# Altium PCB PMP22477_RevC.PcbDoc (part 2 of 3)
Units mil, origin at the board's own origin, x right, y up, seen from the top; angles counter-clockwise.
Board outline 5000 x 3000 mil, 4 copper layers (Top Layer, Signal Layer 1, Signal Layer 2, Bottom Layer), stack 61.2 mil thick; 191 components, 134 nets, 569 pads, 237 vias.
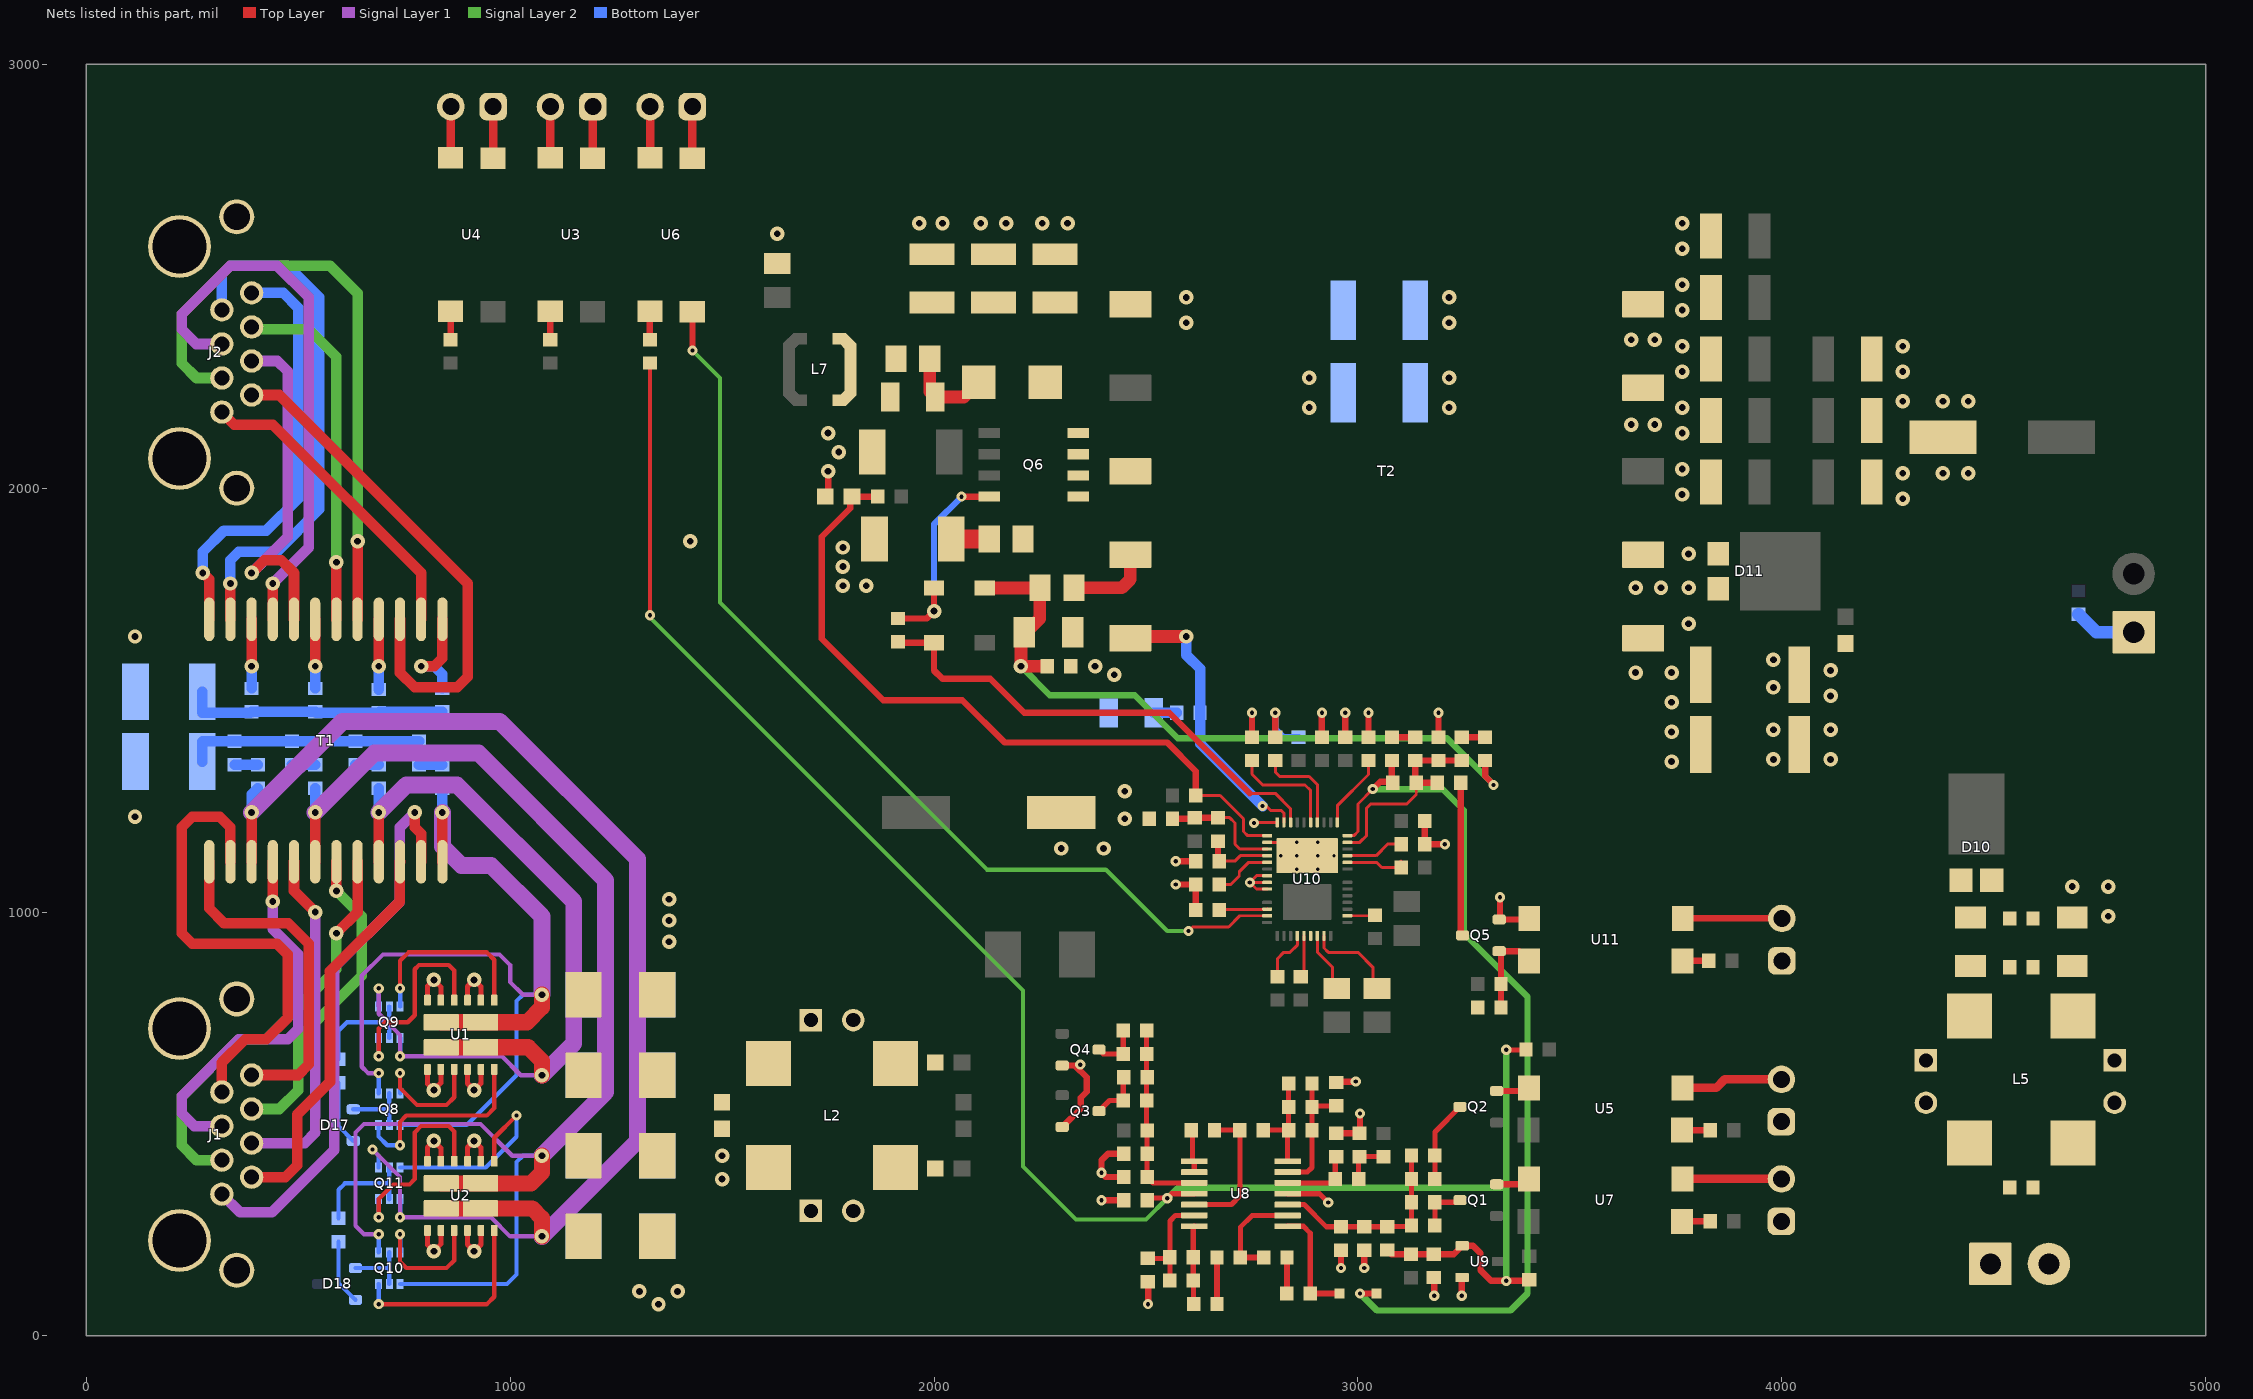
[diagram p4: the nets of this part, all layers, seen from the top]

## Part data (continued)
Q1 Q2 Q3 Q4 Q5: library part CMP-0000769-1, "MOSFET, N-CH, 60 V, 0.17 A, SOT-23", Alternate Manufacturer=None, Manufacturer="Diodes Inc.", Supplier Part Number 1=2N7002-FDICT-ND, Value1=7, Value2="223 nC"
Q6: library part CMP-0001058-1, "MOSFET, N-CH, 150 V, 4.6 A, PQFN08A", Alternate Manufacturer=None, Manufacturer="Fairchild Semiconductor", Supplier Part Number 1=FDMS86252CT-ND, Value1=0, Value2="11 nC"
Q8 Q9 Q10 Q11: library part CMP-0000518-2, "Transistor, NPN/PNP Pair, 65 V, 0.1 A, SOT-363", Manufacturer="Infineon Technologies", Supplier Part Number 1="BC 846PN H6327CT-ND", Value1="0.1 A", Value2=450
R1 R2 R3 R4 R5 R6 R7 R8: library part CMP-0022590-4, "RES, 75.0, 1%, 0.1 W, AEC-Q200 Grade 0, 0603", Manufacturer=Vishay-Dale, PartNumber=CRCW060375R0FKEA, Power_W=100mW, Supplier Part Number 1=541-75.0HCT-ND, TempCo="100 ppm/C", Tolerance_%=1%, Value2=0.1W, Value_Code=75R0, ValueDisplayed=75.0
R9 R10 R11 R12 R13 R15 R20 R35 R44 R56: library part CMP-0021998-4, "RES, 10.0 k, 1%, 0.1 W, AEC-Q200 Grade 0, 0603", Manufacturer=Vishay-Dale, Power_W=100mW, Supplier Part Number 1=541-10.0KHCT-ND, TempCo="100 ppm/C", Tolerance_%=1%, Value2=0.1W, Value_Code=10k0, ValueDisplayed=10.0k
R14 R58: library part CMP-0022458-4, "RES, 4.99 k, 1%, 0.1 W, AEC-Q200 Grade 0, 0603", Manufacturer=Vishay-Dale, Power_W=100mW, Supplier Part Number 1=541-4.99KHCT-ND, TempCo="100 ppm/C", Tolerance_%=1%, Value2=0.1W, Value_Code=4k99, ValueDisplayed=4.99k
R17: library part CMP-0018666-3, "RES, 39 k, 5%, 0.25 W, AEC-Q200 Grade 0, 1206", Manufacturer=Vishay-Dale, PartNumber=CRCW120639K0JNEA, Power_W=250mW, Supplier Part Number 1=541-39KECT-ND, TempCo="200 ppm/C", Tolerance_%=5%, Value2=0.25W, Value_Code=39k0, ValueDisplayed=39k
R18 R26 R34 R38 R39 R40 R72: library part CMP-0022109-5, "RES, 1.00 k, 1%, 0.1 W, AEC-Q200 Grade 0, 0603", Manufacturer=Vishay-Dale, Power_W=100mW, Supplier Part Number 1=541-1.00KHCT-ND, TempCo="100 ppm/C", Tolerance_%=1%, Value2=0.1W, Value_Code=1k00, ValueDisplayed=1.00k
R19: library part CMP-0021990-4, "RES, 100 k, 1%, 0.1 W, AEC-Q200 Grade 0, 0603", Manufacturer=Vishay-Dale, Power_W=100mW, Supplier Part Number 1=541-100KHCT-ND, TempCo="100 ppm/C", Tolerance_%=1%, Value2=0.1W, Value_Code=100k
R21: library part CMP-0022103-4, "RES, 196 k, 1%, 0.1 W, AEC-Q200 Grade 0, 0603", Manufacturer=Vishay-Dale, Power_W=100mW, Supplier Part Number 1=541-196KHCT-ND, TempCo="100 ppm/C", Tolerance_%=1%, Value2=0.1W, Value_Code=196k
R22: library part CMP-0022634-4, "RES, 8.06 k, 1%, 0.1 W, AEC-Q200 Grade 0, 0603", Manufacturer=Vishay-Dale, Power_W=100mW, Supplier Part Number 1=541-8.06KHCT-ND, TempCo="100 ppm/C", Tolerance_%=1%, Value2=0.1W, Value_Code=8k06, ValueDisplayed=8.06k
R23 R36: library part CMP-0022138-4, "RES, 1.00 M, 1%, 0.1 W, AEC-Q200 Grade 0, 0603", Manufacturer=Vishay-Dale, Power_W=100mW, Supplier Part Number 1=541-1.00MHCT-ND, TempCo="100 ppm/C", Tolerance_%=1%, Value2=0.1W, Value_Code=1M00, ValueDisplayed=1.00M
R24: library part CMP-0022284-4, "RES, 2.94 k, 1%, 0.1 W, AEC-Q200 Grade 0, 0603", Manufacturer=Vishay-Dale, Power_W=100mW, Supplier Part Number 1=541-2.94KHCT-ND, TempCo="100 ppm/C", Tolerance_%=1%, Value2=0.1W, Value_Code=2k94, ValueDisplayed=2.94k
R25 R30 R37: library part CMP-0022410-4, "RES, 40.2 k, 1%, 0.1 W, AEC-Q200 Grade 0, 0603", Manufacturer=Vishay-Dale, Power_W=100mW, Supplier Part Number 1=541-40.2KHCT-ND, TempCo="100 ppm/C", Tolerance_%=1%, Value2=0.1W, Value_Code=40k2, ValueDisplayed=40.2k
R27: library part CMP-0022451-4, "RES, 4.22 k, 1%, 0.1 W, AEC-Q200 Grade 0, 0603", Manufacturer=Vishay-Dale, Power_W=100mW, Supplier Part Number 1=541-4.22KHCT-ND, TempCo="100 ppm/C", Tolerance_%=1%, Value2=0.1W, Value_Code=4k22, ValueDisplayed=4.22k
R28: library part CMP-0022256-4, "RES, 280 k, 1%, 0.1 W, AEC-Q200 Grade 0, 0603", Manufacturer=Vishay-Dale, Power_W=100mW, Supplier Part Number 1=541-280KHCT-ND, TempCo="100 ppm/C", Tolerance_%=1%, Value2=0.1W, Value_Code=280k
R29: library part CMP-0022383-4, "RES, 3.92 k, 1%, 0.1 W, AEC-Q200 Grade 0, 0603", Manufacturer=Vishay-Dale, Power_W=100mW, Supplier Part Number 1=541-3.92KHCT-ND, TempCo="100 ppm/C", Tolerance_%=1%, Value2=0.1W, Value_Code=3k92, ValueDisplayed=3.92k
R31: library part CMP-0022131-4, "RES, 1.69 k, 1%, 0.1 W, AEC-Q200 Grade 0, 0603", Manufacturer=Vishay-Dale, Power_W=100mW, Supplier Part Number 1=541-1.69KHCT-ND, TempCo="100 ppm/C", Tolerance_%=1%, Value2=0.1W, Value_Code=1k69, ValueDisplayed=1.69k
R32 R33: library part CMP-0021991-4, "RES, 100, 1%, 0.1 W, AEC-Q200 Grade 0, 0603", Manufacturer=Vishay-Dale, Power_W=100mW, Supplier Part Number 1=541-100HCT-ND, TempCo="100 ppm/C", Tolerance_%=1%, Value2=0.1W, Value_Code=100R, ValueDisplayed=100
R41: library part CMP-0022008-4, "RES, 110 k, 1%, 0.1 W, AEC-Q200 Grade 0, 0603", Manufacturer=Vishay-Dale, Power_W=100mW, Supplier Part Number 1=541-110KHCT-ND, TempCo="100 ppm/C", Tolerance_%=1%, Value2=0.1W, Value_Code=110k
R42 R43: library part CMP-0015887-3, "RES, 15, 5%, 1 W, AEC-Q200 Grade 0, 2512", Manufacturer=Vishay-Dale, Power_W=1W, Supplier Part Number 1=541-15XCT-ND, TempCo="200 ppm/C", Tolerance_%=5%, Value_Code=15R0, ValueDisplayed=15
R45: library part CMP-0021831-3, "RES, 3.90, 1%, 0.125 W, AEC-Q200 Grade 0, 0805", Manufacturer=Panasonic, Power_W=125mW, Supplier Part Number 1=P3.9DCT-ND, TempCo="200 ppm/C", Tolerance_%=1%, Value2=0.125W, Value_Code=3R90, ValueDisplayed=3.90
R46: library part CMP-0018668-3, "RES, 3.0 k, 5%, 0.25 W, AEC-Q200 Grade 0, 1206", Manufacturer=Vishay-Dale, Power_W=250mW, Supplier Part Number 1=541-3.0KECT-ND, TempCo="200 ppm/C", Tolerance_%=5%, Value2=0.25W, Value_Code=3k00, ValueDisplayed=3.0k
R47: library part CMP-0022369-4, "RES, 39.2 k, 1%, 0.1 W, AEC-Q200 Grade 0, 0603", Manufacturer=Vishay-Dale, Power_W=100mW, Supplier Part Number 1=541-39.2KHCT-ND, TempCo="100 ppm/C", Tolerance_%=1%, Value2=0.1W, Value_Code=39k2, ValueDisplayed=39.2k
R48 R49 R52 R55 R59 R60 R65 R73 R101: library part CMP-0025874-4, "RES, 0, 5%, 0.1 W, AEC-Q200 Grade 0, 0603", Manufacturer=Panasonic, Power_W=100mW, Supplier Part Number 1=P0.0GCT-ND, TempCo="600 ppm/C", Tolerance_%=5%, Value2=0.1W, Value_Code=0000, ValueDisplayed=0
R50: library part CMP-0022944-5, "RES, 24.9 k, 1%, 0.1 W, 0603", Manufacturer=Yageo, Power_W=100mW, Supplier Part Number 1=311-24.9KHRCT-ND, TempCo="100 ppm/C", Tolerance_%=1%, Value2=0.1W, Value_Code=24k9, ValueDisplayed=24.9k
R51: library part CMP-0022931-4, "RES, 237 k, 1%, 0.1 W, 0603", Manufacturer=Yageo, Power_W=100mW, Supplier Part Number 1=311-237KHRCT-ND, TempCo="100 ppm/C", Tolerance_%=1%, Value2=0.1W, Value_Code=237k
R53: library part CMP-0022532-4, "RES, 60.4 k, 1%, 0.1 W, AEC-Q200 Grade 0, 0603", Manufacturer=Vishay-Dale, Power_W=100mW, Supplier Part Number 1=541-60.4KHCT-ND, TempCo="100 ppm/C", Tolerance_%=1%, Value2=0.1W, Value_Code=60k4, ValueDisplayed=60.4k
R54: library part CMP-0023050-5, "RES, 35.7 k, 1%, 0.1 W, 0603", Manufacturer=Yageo, Power_W=100mW, Supplier Part Number 1=311-35.7KHRCT-ND, TempCo="100 ppm/C", Tolerance_%=1%, Value2=0.1W, Value_Code=35k7, ValueDisplayed=35.7k
R57 R62: library part CMP-0022204-4, "RES, 20.0 k, 1%, 0.1 W, AEC-Q200 Grade 0, 0603", Manufacturer=Vishay-Dale, Power_W=100mW, Supplier Part Number 1=541-20.0KHCT-ND, TempCo="100 ppm/C", Tolerance_%=1%, Value2=0.1W, Value_Code=20k0, ValueDisplayed=20.0k
R61: library part CMP-0025821-4, "RES, 4.7, 5%, 0.1 W, AEC-Q200 Grade 0, 0603", Manufacturer=Vishay-Dale, Power_W=100mW, Supplier Part Number 1=541-4.7GCT-ND, TempCo="200 ppm/C", Tolerance_%=5%, Value2=0.1W, Value_Code=4R70, ValueDisplayed=4.7
R63: library part CMP-0016178-3, "RES, 75, 5%, 0.75 W, AEC-Q200 Grade 0, 2010", Manufacturer=Vishay-Dale, Power_W=750mW, Supplier Part Number 1=541-75.0WCT-ND, TempCo="200 ppm/C", Tolerance_%=5%, Value2=0.75W, Value_Code=75R0, ValueDisplayed=75
R64: library part CMP-0022447-4, "RES, 49.9 k, 1%, 0.1 W, AEC-Q200 Grade 0, 0603", Manufacturer=Vishay-Dale, Power_W=100mW, Supplier Part Number 1=541-49.9KHCT-ND, TempCo="100 ppm/C", Tolerance_%=1%, Value2=0.1W, Value_Code=49k9, ValueDisplayed=49.9k
R66: library part CMP-0018594-3, "RES, 15, 5%, 0.25 W, AEC-Q200 Grade 0, 1206", Manufacturer=Vishay-Dale, Power_W=250mW, Supplier Part Number 1=541-15ECT-ND, TempCo="200 ppm/C", Tolerance_%=5%, Value2=0.25W, Value_Code=15R0, ValueDisplayed=15
R67: library part CMP-0016520-2, "RES, 0.05, 1%, 1 W, 2010", Manufacturer="Stackpole Electronics Inc", Power_W=1W, Supplier Part Number 1=CSRN2010FK50L0CT-ND, TempCo="250 ppm/C", Tolerance_%=1%, Value_Code=R050, ValueDisplayed=0.05
R68: library part CMP-0021169-3, "RES, 31.6, 1%, 0.125 W, AEC-Q200 Grade 0, 0805", Manufacturer=Vishay-Dale, Power_W=125mW, Supplier Part Number 1=541-31.6CCT-ND, TempCo="100 ppm/C", Tolerance_%=1%, Value2=0.125W, Value_Code=31R6, ValueDisplayed=31.6
R69: library part CMP-0020880-3, "RES, 130, 1%, 0.125 W, AEC-Q200 Grade 0, 0805", Manufacturer=Vishay-Dale, Power_W=125mW, Supplier Part Number 1=541-130CCT-ND, TempCo="100 ppm/C", Tolerance_%=1%, Value2=0.125W, Value_Code=130R, ValueDisplayed=130
R70: library part CMP-0025851-4, "RES, 750 k, 5%, 0.1 W, AEC-Q200 Grade 0, 0603", Manufacturer=Vishay-Dale, Power_W=100mW, Supplier Part Number 1=541-750KGCT-ND, TempCo="200 ppm/C", Tolerance_%=5%, Value2=0.1W, Value_Code=750k
R71: library part CMP-0022951-5, "RES, 25.5 k, 1%, 0.1 W, 0603", Manufacturer=Yageo, Power_W=100mW, Supplier Part Number 1=311-25.5KHRCT-ND, TempCo="100 ppm/C", Tolerance_%=1%, Value2=0.1W, Value_Code=25k5, ValueDisplayed=25.5k
R74: library part CMP-0022445-4, "RES, 499 k, 1%, 0.1 W, AEC-Q200 Grade 0, 0603", Manufacturer=Vishay-Dale, Power_W=100mW, Supplier Part Number 1=541-499KHCT-ND, TempCo="100 ppm/C", Tolerance_%=1%, Value2=0.1W, Value_Code=499k
R75 R76: library part CMP-0022073-4, "RES, 162 k, 1%, 0.1 W, AEC-Q200 Grade 0, 0603", Manufacturer=Vishay-Dale, Power_W=100mW, Supplier Part Number 1=541-162KHCT-ND, TempCo="100 ppm/C", Tolerance_%=1%, Value2=0.1W, Value_Code=162k
R100: library part CMP-0022371-4, "RES, 3.01 k, 1%, 0.1 W, AEC-Q200 Grade 0, 0603", Manufacturer=Vishay-Dale, Power_W=100mW, Supplier Part Number 1=541-3.01KHCT-ND, TempCo="100 ppm/C", Tolerance_%=1%, Value2=0.1W, Value_Code=3k01, ValueDisplayed=3.01k
T1: library part CMP-0030730-1, "Transformer, PoE+, SMT", Manufacturer="Wurth Elektronik", ValueDisplayed=350uH
T2: library part CMP-0088826-2, "Transformer", Frequency_Fixed=250kHz, Manufacturer=LinkCom, Operating Temperature Range=to
U1 U2: library part CMP-0005142-3, "GreenBridge 2 Series of High-Efficiency Bridge Rectifiers", Manufacturer="Fairchild Semiconductor", Supplier Part Number 1=08AC1049
U3 U4 U5 U6 U7 U11: library part CMP-0006165-3, "Optocoupler, 5 kV, 300-600% CTR, SMT", Manufacturer="Fairchild Semiconductor", Supplier Part Number 1=FOD817DS-ND, Voltage_Isolation_Vrms=5kV
U8: library part CMP-0089537-1, "General Purpose Amplifier 4 Circuit Rail-to-Rail 14-TSSOP", Digikey Part Number=296-46609-1-ND, Input Bias Current=0.0000003uA, Input Offset Voltage=0.05mV, Manufacturer="Texas Instruments", Max Dual Supply Voltage=2.75V, Max Supply Voltage=5.5V, Min Dual Supply Voltage=1.1V, Min Supply Voltage=2.2V, Mouser Part Number=595-TLV4376IPWR, Nominal Supply Current=815uA, Operating Temperature Range="-40°C to +125°C", Voltage Gain=126dB
U9: library part CMP-0079018-1, "Precision Micropower Shunt Voltage Reference, DBZ0003A (SOT-23-3)", Alternate Manufacturer="Texas Instruments", Alternate PartNumber=LM4040DIM3X-5.0/NOPB
U10: library part CMP-0860918-1, "TPS23730RMT, RMT0045A (VQFN-45)", Alternate Manufacturer="Texas Instruments"

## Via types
v1: diameter 34, hole 16, Top Layer to Bottom Layer, 127 vias
v2: diameter 24, hole 10, Top Layer to Bottom Layer, 97 vias
v3: diameter 19.68, hole 7.87, Top Layer to Bottom Layer, 13 vias

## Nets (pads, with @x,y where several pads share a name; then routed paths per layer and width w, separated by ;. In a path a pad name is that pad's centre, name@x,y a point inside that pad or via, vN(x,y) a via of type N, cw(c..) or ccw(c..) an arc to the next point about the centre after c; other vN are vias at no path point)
5VREG: C9.2 C14.2 R11.1 R14.1 R15.1 R18.1 R20.2 U8.4 U9.1 | length 4598.8
  Top Layer w10: R14.1@1329.54,2295.35 1330,2294.9 v2(1330,1700)
  Top Layer w12: C14.2@2502.56,320 2507.56,325 v2(2550,325) 2560.46,335.46 U8.4@2613.74,335.46 ; v2(3350,675) 3395.96,675 R11.1@3396.42,675.46
  Top Layer w15: R20.2@3068.98,202.9 3079.32,192.56 R18.1@3125,192.56 3178.52,192.56 C9.2@3178.98,193.02 3225.83,193.02 U9.1@3245.67,212.86 3271.26,212.86 3288.98,195.14 3288.98,155 3313.98,130 v2(3350,130) 3401.08,130 R15.1@3403.98,132.9
  Signal Layer 2 w10: v2(1330,1700) 1330,1695 2210,815 2210,400 2335,275 2500,275 v2(2550,325)
  Signal Layer 2 w15: v2(2550,325) 2575,350 3350,350 ; v2(3350,130) 3350,350 ; v2(3350,675) 3350,350
BSP: C1.1 C6.2 J1.9 J1.10 J1.11 J1.12 J2.9 J2.10 J2.11 J2.12
  other v1: 115,1225 115,1650
BT: U6.2 U10.12 | length 2340.5
  Top Layer w7: v2(2600,955) 2610,965 2695,965 2721.26,991.26 U10.12@2786.02,991.26
  Top Layer w15: U6.2@1429.54,2416.32 1430,2415.86 v2(1430,2325)
  Signal Layer 2 w10: v2(1430,2325) 1495,2260 1495,1730 2125,1100 2405,1100 2550,955 v2(2600,955)
COMP: C41.2 C43.2 D9.2 U10.35 | length 2150.1
  Top Layer w7: U10.35@2975,1180.24 2990.24,1180.24 3000,1190 3000,1255 v2(3035,1290)
  Top Layer w15: v2(3005,100) D9.2@3043.31,100 ; v2(3035,1290) 3052.44,1307.44 3080,1307.44 C41.2@3080,1357.44
  Signal Layer 2 w15: v2(3005,100) 3045,60 3360,60 3400,100 3400,800 3250,950 3250,1240 3200,1290 v2(3035,1290)
CP: C50.1 T2.5 U10.44 | length 686.9
  Top Layer w7: v2(2775,1250) 2783.54,1250 2793.54,1240 2818.7,1240 2825.39,1233.31 U10.44@2825.39,1211.73
  Top Layer w30: T2.5@2463.11,1646.22 2466.89,1650 v1(2595,1650)
  Bottom Layer w25: v1(2595,1650) 2595,1606.3 2627.56,1573.74 C50.1@2627.56,1470 2627.56,1397.44 v2(2775,1250)
CS: C51.2 R70.1 R72.1 U10.1 | length 1722.6
  Top Layer w7: R70.1@2617.56,1275 2675,1275 2730,1220 2730,1190 2739.76,1180.24 U10.1@2786.02,1180.24
  Top Layer w15: R72.1@1867.44,1980 1802.56,1980 1802.56,1952.56 1735,1885 1735,1645 1880,1500 2066.69,1500 2166.69,1400 2550,1400 2617.56,1332.44 R70.1@2617.56,1275
GND: C15.2 C21.1 C22.1 C29.2 C30.1 C31.1 C32.1 C33.1 C34.1 C35.1 C36.2 C52.1 C53.1 J5.1 J6.1 J7.1 J8.1 J9.1 J13.1 J14.1 L6.1 T2.9 T2.10 U3.3 U4.3 U6.3 | length 515.5
  Top Layer w20: U4.3@959.54,2778.52 960,2778.98 J6.1@960,2900 ; U3.3@1194.54,2778.52 1195,2778.98 J5.1@1195,2900 ; U6.3@1429.54,2778.52 1430,2778.98 J8.1@1430,2900
  Top Layer w25: L6.1@4682.91,985 L6.1@4685,987.09
  Bottom Layer w30: C36.2@4700,1702.44 4742.44,1660 J13.1@4830,1660
  other v1: 4770,990 4685,1060 4770,1060 4285,1975 3764.59,1985 4285,2035 4380,2035 4440,2035 3765,2045 3765,2130 3645,2150 3700,2150 3215,2190 3765,2190 4285,2205 4380,2205 4440,2205 3215,2260 3765,2275 4285,2275 3765,2335 4285,2335 3645,2350 3700,2350 3215,2390 3765,2420 3215,2450 3765,2480 3765,2565 3765,2625
NetC1_2: C1.2 R1.2 R2.2 R3.2 R4.1 | length 619.1
  Bottom Layer w25: C1.2@273.74,1520 273.74,1470.66 274.52,1469.88 387.44,1469.88 R4.1@390,1472.44 R3.2@540,1472.44 542.56,1469.88 R2.2@690,1469.88 692.56,1472.44 R1.2@840,1472.44
NetC2_2: C2.2 R5.2 | length 55
  Bottom Layer w25: R5.2@785,1347.44 839.88,1347.44 C2.2@840,1347.56
NetC3_2: C3.2 R6.2 | length 55
  Bottom Layer w25: R6.2@635,1347.44 689.88,1347.44 C3.2@690,1347.56
NetC4_2: C4.2 R7.2 | length 55
  Bottom Layer w25: R7.2@485,1347.44 539.88,1347.44 C4.2@540,1347.56
NetC5_2: C5.2 R8.2 | length 55
  Bottom Layer w25: R8.2@350,1347.44 404.88,1347.44 C5.2@405,1347.56
NetC6_1: C6.1 R5.1 R6.1 R7.1 R8.1 | length 558.1
  Bottom Layer w25: C6.1@273.74,1355 273.74,1401.3 275,1402.56 R8.1@350,1402.56 R7.1@485,1402.56 R6.1@635,1402.56 R5.1@785,1402.56
NetC7_1: C7.1 D1.1 D2.1 D3.1 D4.1 J3.1 L2.2 U1.5 U1.6 U1.7 U1.8 U2.5 U2.6 U2.7 U2.8 | length 438.6
  Top Layer w12: U2.7@805,248.78 805,215 v1(820,200) 836.5,216.5 U2.8@836.5,248.78 ; U2.6@805,412.17 805,445 v1(820,460) 836.5,443.5 U2.5@836.5,412.17 ; U1.7@805,628.78 805,595 v1(820,580) 836.5,596.5 U1.8@836.5,628.78 ; U1.6@805,792.17 805,825 v1(820,840) 836.5,823.5 U1.5@836.5,792.17
  other v1: 1375,930 1375,980 1375,1030
NetC7_2: C7.2 D5.2 D6.2 D7.2 D8.2 J4.1 L2.3 U1.2 U1.3 U1.10 U1.11 U2.2 U2.3 U2.10 U2.11 | length 438.6
  Top Layer w12: U2.10@899.49,248.78 899.49,215.51 v1(915,200) 930.98,215.98 U2.11@930.98,248.78 ; U2.3@899.49,412.17 899.49,444.49 v1(915,460) 930.98,444.02 U2.2@930.98,412.17 ; U1.10@899.49,628.78 899.49,595.51 v1(915,580) 930.98,595.98 U1.11@930.98,628.78 ; U1.3@899.49,792.17 899.49,824.49 v1(915,840) 930.98,824.02 U1.2@930.98,792.17
  other v1: 1350,75 1305,105 1395,105 1500,370 1500,425
NetC10_2: C10.2 R20.1 R21.1 R22.1 R23.2 R24.1 R25.1 U8.10 | length 480.1
  Top Layer w12: U8.10@2834.21,309.87 2873.07,309.87 2925.38,257.56 R25.1@2960,257.56 C10.2@3015,257.56 3068.52,257.56 R20.1@3068.98,258.02 3123.98,258.02 R21.1@3126.42,260.46 R22.1@3126.42,315.46 R23.2@3126.42,370.46 R24.1@3126.42,425.46
NetC11_2: C11.2 R19.1 R27.2 R28.1 R29.1 R30.1 R31.1 U8.3 | length 462.8
  Top Layer w12: R31.1@2501.54,720.46 R30.1@2501.54,665.46 2501.54,610.46 R28.1@2501.54,555.46 2501.54,486.02 R19.1@2502.56,485 R27.2@2502.56,430 C11.2@2502.56,375 2516.51,361.05 U8.3@2613.74,361.05
NetC12_2: C12.2 R32.1 U8.12 | length 169.6
  Top Layer w12: U8.12@2834.21,361.05 2937.01,361.05 R32.1@2946.42,370.46 2946.42,420.34 C12.2@2948.98,422.9
NetC13_2: C13.2 R32.2 R33.1 | length 108.5
  Top Layer w12: R32.2@3001.54,370.46 3001.54,420.46 C13.2@3003.98,422.9 R33.1@3058.98,422.9
NetC15_1: C15.1 D10.1 D10.2 L4.1
NetC16_1: C16.1 R100.2 | length 85
  Top Layer w15: R100.2@2832.44,100 2832.56,100.12 C16.1@2832.56,185
NetC16_2: C16.2 R35.1 U8.9 | length 249.5
  Top Layer w12: R35.1@2722.56,185 2722.56,256.48 2750.36,284.28 U8.9@2834.21,284.28
  Top Layer w15: R35.1@2722.56,185 C16.2@2777.44,185
NetC17_1: C17.1 R36.1 R37.2 R39.1 U8.13 | length 318.2
  Top Layer w12: U8.13@2834.21,386.64 2880.61,386.64 2891.54,397.56 R36.1@2891.54,485.46 R37.2@2891.54,540.46 ; C17.1@2891.54,595.46 R37.2@2891.54,540.46 ; R39.1@2948.98,542.9 2893.98,542.9 R37.2@2891.54,540.46
NetC17_2: C17.2 R34.2 R36.2 R37.1 U8.14 | length 239.6
  Top Layer w12: R34.2@2776.54,485.46 2832.01,485.46 2834.21,483.25 U8.14@2834.21,412.23 ; R36.2@2836.42,485.46 R37.1@2836.42,540.46 C17.2@2836.42,595.46
NetC18_1: C18.1 R38.2 R40.2 U8.6 | length 257.1
  Top Layer w12: R40.2@2503.98,183.02 2553.98,183.02 R38.2@2556.42,185.46 ; C18.1@2556.42,130.46 R38.2@2556.42,185.46 ; U8.6@2613.74,284.28 2569.29,284.28 2556.42,271.4 R38.2@2556.42,185.46
NetC18_2: C18.2 R38.1 R101.1 U8.7 | length 185
  Top Layer w12: R101.1@2612.44,75 2612.44,129.55 C18.2@2611.54,130.46 R38.1@2611.54,185.46 2611.54,256.48 U8.7@2613.74,258.69
NetC19_1: C19.1 J12.1 L5.3 L6.2 | length 7
  Top Layer w25: L6.2@4682.09,870 L6.2@4685,872.91
  Top Layer w50: L5.3@4685,756.65 L5.3@4687.05,754.61
NetC19_2: C19.2 J10.1 L4.2 L5.4 | length 1.2
  Top Layer w25: L4.2@4442.95,870.87 L4.2@4443.82,870
NetC20_1: C20.1 J11.2 J12.2 L5.2
NetC20_2: C20.2 J10.2 J11.1 L5.1
NetC22_2: C22.2 C25.1 C26.1 C27.1 C28.2 L7.2 R17.2 T2.1
  other v1: 2595,2390 2595,2450
NetC28_1: C28.1 D12.1 R17.1 | length 211.8
  Top Layer w30: C28.1@1990,2305 1990,2228.15 R17.1@2003.15,2215 2070,2215 D12.1@2105,2250
NetC37_2: C37.2 R42.2 R43.2
  other v1: 3980,1360 4115,1360 3980,1430 4115,1430 4115,1510 3980,1530 4115,1570 3980,1595
NetC40_1: C40.1 D14.2 R45.1 R46.2 R48.2 | length 1691.5
  Top Layer w15: R48.2@3300,1357.44 3300,1320 v2(3320,1300)
  Top Layer w30: D14.2@2120,1764.47 2249.47,1764.47 2249.47,1692.62 2216.85,1660 2205,1648.15 v1(2205,1580) C40.1@2267.44,1580
  Signal Layer 2 w15: v1(2205,1580) 2273.27,1511.73 2473.27,1511.73 2575,1410 3210,1410 v2(3320,1300)
NetC41_1: C41.1 R47.1 | length 55
  Top Layer w15: C41.1@3080,1412.56 R47.1@3135,1412.56
NetC43_1: C43.1 R47.2 R50.1 R54.1 R58.1 U10.34 | length 488.5
  Top Layer w7: U10.34@2975,1164.49 3004.49,1164.49 3020,1180 3020,1245 3030,1255 3115.28,1255 3137.56,1277.28 C43.1@3137.56,1305
  Top Layer w15: R54.1@3187.44,1305 C43.1@3137.56,1305 3135,1307.56 R47.2@3135,1357.44 R58.1@3190,1357.44 R50.1@3245,1357.44
NetC46_1: C46.1 R51.1 R52.2 U10.3 | length 284.4
  Top Layer w7: R51.1@2670,1222.56 2697.44,1222.56 2710,1210 2710,1160 2721.26,1148.74 U10.3@2786.02,1148.74
  Top Layer w15: C46.1@2562.56,1220 2612.44,1220 R52.2@2615,1222.56 R51.1@2670,1222.56
NetC47_2: C47.2 U10.40 | length 261.5
  Top Layer w7: C47.2@2750,1357.44 2750,1325.24 2775.24,1300 2875,1300 2888.39,1286.61 U10.40@2888.39,1211.73
NetC49_1: C49.1 R63.1 | length 89.4
  Top Layer w45: R63.1@2040.55,1880 C49.1@2130,1880
NetC49_2: C49.2 D12.2 Q6.5 Q6.6 Q6.7 Q6.8 T2.3
NetC50_2: C50.2 R66.1 | length 54.3
  Bottom Layer w25: R66.1@2518.15,1470 C50.2@2572.44,1470
NetD9_1: D9.1 R100.1 U8.8 | length 271.7
  Top Layer w12: U8.8@2834.21,258.69 2871.31,258.69 2887.56,242.44 R100.1@2887.56,100
  Top Layer w15: R100.1@2887.56,100 D9.1@2956.69,100
NetD11_1: D11.1 D11.2 R42.1 R43.1 T2.6 T2.7
  other v1: 3740,1355 3740,1425 3740,1495 3655,1565 3740,1565 3780,1680 3655,1765 3715,1765 3780,1765 3780,1845
NetD15_1: D15.1 R61.1 U10.43 | length 1159.7
  Top Layer w7: 2745,1280 2805,1280 2841.14,1243.86 U10.43@2841.14,1211.73
  Top Layer w15: R61.1@1915,1637.44 1916.91,1635.53 D15.1@2000,1635.53 2000,1570 2020,1550 2132.54,1550 2212.54,1470 2555,1470 2745,1280
NetD15_2: D15.2 Q6.4 R61.2 | length 508.6
  Top Layer w15: R61.2@1915,1692.56 1982.56,1692.56 v1(2000,1710) D15.2@2000,1764.47 ; v2(2065,1980) Q6.4@2130,1980
  Bottom Layer w15: v1(2000,1710) 2000,1915 v2(2065,1980)
NetD17_1: D17.1 Q8.2 Q8.5 | length 159.9
  Bottom Layer w10: D17.1@630,534.8 630.19,534.99 715,534.99 ; Q8.2@715,497.6 715,534.99 ; Q8.5@715,572.4 715,534.99
NetD17_2: D17.2 R75.2 | length 151.9
  Bottom Layer w10: R75.2@595,597.44 595,495 D17.2@630,460
NetD18_1: D18.1 Q10.2 Q10.5 | length 154.8
  Bottom Layer w10: D18.1@635,160 715,159.99 ; Q10.2@715,122.6 715,159.99 ; Q10.5@715,197.4 715,159.99
NetD18_2: D18.2 R76.2 | length 153.8
  Bottom Layer w10: R76.2@595,222.44 595,125.2 D18.2@635,85.2
NetJ1_1: J1.1 T1.23 | length 1341.5
  Top Layer w25: v1(775,1235) 775,1199.96 790.04,1184.92 T1.23@790.04,1118.63
  Signal Layer 1 w25: J1.1@319.96,334.53 363.15,291.34 437.61,291.34 585,438.73 585,870 740,1025 740,1200 v1(775,1235)
NetJ1_2: J1.2 T1.22 | length 935.6
  Top Layer w25: J1.2@390.04,374.68 469.68,374.68 497.5,402.5 497.5,522.5 575,600 575,860 740,1025 T1.22@740.04,1118.63 T1.22@740.04,1118.63
NetJ1_3: J1.3 T1.20 | length 988.2
  Top Layer w25: v1(590,950) 640.04,1000.04 T1.20@640.04,1118.63 T1.20@640.04,1118.63
  Signal Layer 2 w25: J1.3@319.96,414.84 260.16,414.84 225,450 225,565 360,700 425,700 590,865 v1(590,950)
NetJ1_4: J1.4 T1.17 | length 819.7
  Top Layer w25: T1.17@490.04,1118.63 490.04,1050 v1(540.04,1000)
  Signal Layer 1 w25: J1.4@390.04,455 515,455 540.04,480.04 v1(540.04,1000)
NetJ1_5: J1.5 T1.16 | length 907.1
  Top Layer w25: v1(440,1025) T1.16@440.04,1118.63 T1.16@440.04,1118.63
  Signal Layer 1 w25: J1.5@319.96,495.16 254.84,495.16 225,525 225,565 360,700 475,700 500,725 500,900 440,960 v1(440,1025)
NetJ1_6: J1.6 T1.19 | length 754.1
  Top Layer w25: v1(590,1050) T1.19@590.04,1118.63 T1.19@590.04,1118.63
  Signal Layer 2 w25: J1.6@390.04,535.31 455.31,535.31 500,580 500,700 650,850 650,990 v1(590,1050)
NetJ1_7: J1.7 T1.14 | length 1155.8
  Top Layer w25: J1.7@319.96,575.47 319.96,644.96 375,700 425,700 475,750 475,900 450,925 250,925 225,950 225,1200 250,1225 315,1225 340.04,1199.96 T1.14@340.04,1118.63
NetJ1_8: J1.8 T1.13 | length 809.2
  Top Layer w25: T1.13@290.04,1118.63 290.04,1008.7 325,973.74 476.26,973.74 525,925 525,640.63 500,615.63 J1.8@390.04,615.63
NetJ2_1: J2.1 T1.2 | length 736.6
  Top Layer w25: J2.1@319.96,2179.53 349.49,2150 440,2150 790.04,1799.96 T1.2@790.04,1690.63
NetJ2_2: J2.2 T1.3 | length 1224.6
  Top Layer w25: J2.2@390.04,2219.68 455.32,2219.68 900,1775 900,1555 875,1530 775,1530 740.04,1564.96 T1.3@740.04,1690.63
NetJ2_3: J2.3 T1.5 | length 1483.5
  Top Layer w25: v1(640,1875) 640,1690.67 T1.5@640.04,1690.63
  Signal Layer 2 w25: J2.3@319.96,2259.84 260.16,2259.84 225,2295 225,2410 340,2525 575,2525 640,2460 v1(640,1875)
NetJ2_4: J2.4 T1.8 | length 840.2
  Top Layer w25: v1(390,1800) 420,1830 460,1830 490.04,1799.96 T1.8@490.04,1690.63
  Signal Layer 1 w25: v1(390,1800) 475,1885 475,2275.67 450.67,2300 J2.4@390.04,2300
NetJ2_5: J2.5 T1.9 | length 1317.7
  Top Layer w25: v1(440,1775) v1(440,1775) T1.9@440.04,1690.63
  Signal Layer 1 w25: J2.5@319.96,2340.16 259.84,2340.16 225,2375 225,2410 340,2525 450,2525 525,2450 525,1860 v1(440,1775)
NetJ2_6: J2.6 T1.6 | length 848.5
  Top Layer w25: v1(590,1825) 590,1690.67 T1.6@590.04,1690.63
  Signal Layer 2 w25: J2.6@390.04,2380.31 395.35,2375 525,2375 590,2310 v1(590,1825)
NetJ2_7: J2.7 T1.11 | length 1253
  Top Layer w25: v1(340,1775) v1(340,1775) T1.11@340.04,1690.63
  Bottom Layer w25: J2.7@319.96,2420.47 319.96,2504.96 340,2525 475,2525 550,2450 550,1950 450,1850 360.04,1850 340,1829.96 v1(340,1775)
NetJ2_8: J2.8 T1.12 | length 1017.1
  Top Layer w25: v1(275,1800) 290.04,1784.96 T1.12@290.04,1690.63
  Bottom Layer w25: v1(275,1800) 275,1850 325,1900 425,1900 500,1975 500,2425 464.37,2460.63 J2.8@390.04,2460.63
NetJ3_2: J3.2 L1.1 L2.1
NetJ4_2: J4.2 L2.4 L3.1
NetJ5_2: J5.2 U3.4 | length 120.7
  Top Layer w20: U3.4@1094.54,2779.51 1095,2779.96 J5.2@1095,2900
NetJ6_2: J6.2 U4.4 | length 120.7
  Top Layer w20: U4.4@859.54,2779.51 860,2779.96 J6.2@860,2900
NetJ7_2: J7.2 U5.2 | length 241.7
  Top Layer w20: U5.2@3765.57,585.46 3845.46,585.46 3865.46,605.46 J7.2@3998.98,605.46
NetJ8_2: J8.2 U6.4 | length 120.7
  Top Layer w20: U6.4@1329.54,2779.51 1330,2779.96 J8.2@1330,2900
NetJ9_2: J9.2 U7.2 | length 233.4
  Top Layer w20: U7.2@3765.57,370.46 J9.2@3998.98,370.46
NetJ14_2: J14.2 U11.2 | length 233.4
  Top Layer w15: U11.2@3766.59,985 J14.2@4000,985
NetQ1_3: Q1.3 R21.2 R22.2 | length 116.2
  Top Layer w12: R21.2@3181.54,260.46 R22.2@3181.54,315.46 3235.67,315.46 Q1.3@3240.67,320.46
NetQ2_3: Q2.3 R23.1 R24.2 | length 194.5
  Top Layer w12: R23.1@3181.54,370.46 R24.2@3181.54,425.46 3181.54,481.32 Q2.3@3240.67,540.46
NetQ3_3: Q3.3 R28.2 R29.2 | length 122.8
  Top Layer w12: Q3.3@2388.98,530.46 2413.98,555.46 R28.2@2446.42,555.46 R29.2@2446.42,610.46
NetQ4_3: Q4.3 R30.2 R31.2 | length 116.6
  Top Layer w12: Q4.3@2388.98,675.46 2398.98,665.46 R30.2@2446.42,665.46 R31.2@2446.42,720.46
NetQ5_1: Q5.1 R57.2 R62.1 U11.4 | length 213.8
  Top Layer w15: R62.1@3337.56,775 R57.2@3337.56,830 3337.56,903.35 Q5.1@3333.31,907.6 3380.81,907.6 U11.4@3403.41,885
NetQ5_3: Q5.3 R54.2 | length 361.7
  Top Layer w15: R54.2@3242.56,1305 3242.56,949.13 Q5.3@3246.69,945
NetQ8_3: Q8.3 U1.12 | length 468.4
  Top Layer w10: v2(740,450) 740,505 755,520 945,520 962.48,537.48 U1.12@962.48,628.78
  Bottom Layer w10: Q8.3@689.41,497.6 689.41,470.59 710,450 v2(740,450)
NetQ8_6: Q8.6 U1.9 | length 300.6
  Top Layer w10: v2(740,620) 740,585 780,545 850,545 867.99,562.99 U1.9@867.99,628.78
  Bottom Layer w10: v2(740,620) 740,572.99 Q8.6@740.59,572.4
NetQ9_2: Q9.2 Q9.5 R75.1 | length 270.5
  Bottom Layer w10: R75.1@595,652.56 595,720 615,740 715,740 ; Q9.5@715,702.6 715,740 ; Q9.2@715,777.4 715,740
NetQ9_3: Q9.3 U1.1 | length 441.2
  Top Layer w10: v2(740,820) 740,885 760,905 945,905 962.48,887.52 U1.1@962.48,792.17
  Bottom Layer w10: v2(740,820) 740.59,819.41 Q9.3@740.59,777.4
NetQ9_6: Q9.6 U1.4 | length 486.6
  Top Layer w10: v2(690,660) 690,725 705,740 758.3,740 775,756.7 775,865 785,875 855,875 867.99,862.01 U1.4@867.99,792.17
  Bottom Layer w10: Q9.6@689.41,702.6 689.41,660.59 v2(690,660)
NetQ10_3: Q10.3 U2.12 | length 483.9
  Top Layer w10: v2(690,75) 945,75 962.48,92.48 U2.12@962.48,248.78
  Bottom Layer w10: Q10.3@689.41,122.6 690,122.01 v2(690,75)
NetQ10_6: Q10.6 U2.9 | length 320.3
  Top Layer w10: v2(740,240) 740,175 755,160 850,160 867.99,177.99 U2.9@867.99,248.78
  Bottom Layer w10: v2(740,240) 740.59,239.41 Q10.6@740.59,197.4
NetQ11_2: Q11.2 Q11.5 R76.1 | length 268.5
  Bottom Layer w10: R76.1@595,277.56 595,345 610,360 715,360 ; Q11.5@715,322.6 715,360 ; Q11.2@715,397.4 715,360
NetQ11_3: Q11.3 U2.1 | length 484.1
  Top Layer w10: U2.1@962.48,412.17 962.48,467.48 v2(1015,520)
  Bottom Layer w10: Q11.3@740.59,397.4 942.4,397.4 1015,470 v2(1015,520)
NetQ11_6: Q11.6 U2.4 | length 474.9
  Top Layer w10: v2(690,280) 690,323.19 724.34,357.52 762.52,357.52 775,370 775,480.04 789.96,495 855,495 867.99,482.01 U2.4@867.99,412.17
  Bottom Layer w10: Q11.6@689.41,322.6 689.41,280.59 v2(690,280)
NetR1_1: R1.1 T1.1 | length 241.2
  Top Layer w25: v1(790,1580) 821.3,1580 840.04,1598.74 T1.1@840.04,1690.63
  Bottom Layer w25: v1(790,1580) 821.3,1580 840,1561.3 R1.1@840,1527.56
NetR2_1: R2.1 T1.4 | length 165.6
  Top Layer w25: v1(690,1580) T1.4@690.04,1690.63 T1.4@690.04,1690.63
  Bottom Layer w25: R2.1@690,1525 v1(690,1580)
NetR3_1: R3.1 T1.7 | length 163.1
  Top Layer w25: v1(540,1580) T1.7@540.04,1690.63 T1.7@540.04,1690.63
  Bottom Layer w25: R3.1@540,1527.56 v1(540,1580)
NetR4_2: R4.2 T1.10 | length 163.1
  Top Layer w25: v1(390,1580) T1.10@390.04,1690.63 T1.10@390.04,1690.63
  Bottom Layer w25: R4.2@390,1527.56 v1(390,1580)
NetR9_1: R9.1 U3.1 | length 66.8
  Top Layer w15: R9.1@1094.54,2350.47 U3.1@1094.54,2417.3
NetR10_1: R10.1 U4.1 | length 66.8
  Top Layer w15: R10.1@859.54,2350.47 U4.1@859.54,2417.3
NetR12_2: R12.2 U5.1 | length 66.8
  Top Layer w15: U5.1@3764.59,485.46 R12.2@3831.42,485.46
NetR13_2: R13.2 U7.1 | length 66.8
  Top Layer w15: U7.1@3764.59,270.46 R13.2@3831.42,270.46
NetR14_2: R14.2 U6.1 | length 66.8
  Top Layer w15: R14.2@1329.54,2350.47 U6.1@1329.54,2417.3
NetR26_1: R26.1 U8.1 U8.2 | length 101.9
  Top Layer w12: R26.1@2606.42,485.46 2610,481.87 2610,415 2613.74,411.26 U8.2@2613.74,386.64
NetR26_2: R26.2 R34.1 U8.5 | length 331.5
  Top Layer w12: U8.5@2613.74,309.87 2701.55,309.87 2721.42,329.73 R34.1@2721.42,485.46 R26.2@2661.54,485.46
NetR35_2: R35.2 R101.2 | length 110
  Top Layer w15: R35.2@2667.44,185 2667.56,184.88 R101.2@2667.56,75
NetR45_2: R45.2 T2.4 | length 199.5
  Top Layer w30: R45.2@2330,1765 2443.11,1765 2463.11,1785 T2.4@2463.11,1843.07
NetR48_1: R48.1 R50.2 | length 55
  Top Layer w15: R50.2@3245,1412.56 R48.1@3300,1412.56
NetR49_1: R49.1 U10.36 | length 176.2
  Top Layer w7: U10.36@2951.38,1211.73 2951.38,1250.87 3025,1324.49 R49.1@3025,1357.44
NetR51_2: R51.2 R53.2 U10.4 | length 167.3
  Top Layer w7: R53.2@2672.56,1120 2709.54,1120 2722.54,1132.99 U10.4@2786.02,1132.99
  Top Layer w15: R51.2@2670,1167.44 2670,1122.56 R53.2@2672.56,1120
NetR55_1: R55.1 U10.39 | length 227.5
  Top Layer w7: R55.1@2805,1357.44 2805,1330.47 2815.47,1320 2885,1320 2904.13,1300.87 U10.39@2904.13,1211.73
NetR56_2: R56.2 U11.1 | length 61.8
  Top Layer w15: U11.1@3765.61,885 R56.2@3827.44,885
NetR59_2: R59.2 U10.5 | length 141
  Top Layer w7: R59.2@2672.56,1065 2700,1065 2720,1085 2720,1095 2742.24,1117.24 U10.5@2786.02,1117.24
NetR60_2: R60.2 U10.11 | length 114.3
  Top Layer w7: R60.2@2672.56,1005 2673.69,1006.13 2770.22,1006.13 2770.65,1006.57 2785.59,1006.57 U10.11@2786.02,1007.01
NetR64_2: R64.2 U10.17 | length 124.7
  Top Layer w7: R64.2@2810,847.56 2810,890 2825,905 2840,905 2856.89,921.89 U10.17@2856.89,944.02
NetR65_2: R65.2 U10.18 | length 99.6
  Top Layer w7: R65.2@2865,847.56 2872.64,855.2 U10.18@2872.64,944.02
NetR68_2: R68.2 U10.21 | length 212.7
  Top Layer w7: U10.21@2919.88,944.02 2919.88,915.12 2930,905 3000,905 3035,870 R68.2@3035,820
NetR69_2: R69.2 U10.20 | length 138.9
  Top Layer w7: U10.20@2904.13,944.02 2904.13,905.87 2940,870 R69.2@2940,820
NetR71_2: R71.2 U10.24 | length 65.5
  Top Layer w7: U10.24@2975,991.26 3038.7,991.26 R71.2@3040,992.56
NetR73_2: R73.2 U10.31 | length 135
  Top Layer w7: U10.31@2975,1117.24 3044.06,1117.24 3056.3,1105 R73.2@3102.44,1105 ; R73.2@3099.65,1118.69 R73.2@3101.42,1120.46
NetR74_2: R74.2 U10.32 | length 138.6
  Top Layer w7: U10.32@2975,1132.99 3042.99,1132.99 3070,1160 R74.2@3102.44,1160
PGND: C9.1 C10.1 C11.1 C12.1 C13.1 C14.1 C21.2 C23.2 C24.2 C25.2 C26.2 C27.2 C38.2 C40.2 C44.2 C45.2 C46.2 C47.1 C51.1 Q1.2 Q2.2 Q3.2 Q4.2 Q5.2 R25.2 R27.1 R39.2 R40.1 R44.1 R46.1 R49.2 R53.1 R55.2 R58.2 R59.1 R60.1 R62.2 R63.2 R66.2 R67.2 R74.1 U5.3 U7.3 U8.11 U9.2 U10.2 U10.7 U10.8 U10.9 U10.45 U10.46 U11.3 | length 2234.9
  Top Layer w7: v2(2755,1210) 2756.73,1211.73 U10.45@2809.65,1211.73 ; U10.9@2786.02,1054.25 2760.75,1054.25 v2(2745,1070) ; U10.8@2786.02,1070 v2(2745,1070) ; U10.7@2786.02,1085.75 2760.75,1085.75 v2(2745,1070) ; U10.2@2786.02,1164.49 2849.02,1164.49 U10.46@2880.51,1132.99
  Top Layer w12: U8.11@2834.21,335.46 2909.54,335.46 v2(2930,315)
  Top Layer w15: C51.1@1747.44,1980 1750,1982.56 v1(1750,2040) ; Q3.2@2302.36,493.06 2345.67,536.36 2345.67,561.76 2360,576.09 2360,610 2331.94,638.06 Q4.2@2302.36,638.06 ; v2(2395,320) C14.1@2447.44,320 ; C11.1@2447.44,375 2405,375 v2(2395,385) 2395,414.63 2410.37,430 R27.1@2447.44,430 ; R40.1@2503.98,127.9 2505,126.87 v2(2505,75) ; v2(2570,1065) R59.1@2617.44,1065 R60.1@2617.44,1005 ; v2(2570,1120) R53.1@2617.44,1120 ; C47.1@2750,1412.56 v2(2750,1470) ; R55.2@2805,1412.56 v2(2805,1470) ; R44.1@2915,1412.56 v2(2915,1470) ; C12.1@2948.98,478.02 C13.1@3003.98,478.02 3005,479.04 v2(3005,525) ; R39.2@2948.98,598.02 2950.96,600 v2(2995,600) ; v2(2960,160) R25.2@2960,202.44 ; C45.2@2970,1412.56 v2(2970,1470) ; v2(3015,160) C10.1@3015,202.44 ; R49.2@3025,1412.56 v2(3025,1470) ; C38.2@3157.56,1215 R74.1@3157.56,1160 v2(3205,1160) ; C9.1@3178.98,137.9 3180,136.87 v2(3180,95) ; R58.2@3190,1412.56 v2(3190,1470) ; v2(3245,95) 3245,137.39 U9.2@3245.67,138.06 ; Q1.2@3327.28,357.86 3390.77,357.86 U7.3@3403.37,370.46 ; Q2.2@3327.28,577.86 3395.77,577.86 U5.3@3403.37,585.46 ; v2(3335,1035) 3335,984.09 Q5.2@3333.31,982.4 3401.79,982.4 U11.3@3404.39,985
  Bottom Layer w15: v2(2805,1470) 2805,1432.24 2824.69,1412.56 C44.2@2860,1412.56
  other v1: 2300,1150 2400,1150 2450,1220 2450,1285 2425,1560 2380,1580 1785,1770 1840,1770 1785,1815 1785,1860 1425,1875 1775,2085 1750,2130 2885,2190 2885,2260 1630,2600 1965,2625 2020,2625 2110,2625 2170,2625 2255,2625 2315,2625
  other v2: 2345,640
  other v3: 2855.91,1101.3 2905.12,1101.3 2817.52,1132.99 2855.91,1132.99 2905.12,1132.99 2943.5,1132.99 2855.91,1164.68 2905.12,1164.68
PPD: U10.19
PR12: C2.1 D1.2 D5.1 Q8.1 Q8.4 T1.24 U1.13 U1.14 | length 2405.8
  Top Layer w25: v1(840,1235) v1@840,1225 ; T1.24@840.04,1118.63 v1@840,1225 ; v1@840.04,1224.96 v1@840,1225
  Top Layer w38: U1.14@837.48,740 U1.13@930,740 1040,740 1075,775 v1(1075,805)
  Signal Layer 1 w10: v2(689.88,620) 665,620 650,635 650,850 700,900 975,900 1000,875 1000,835 1030,805 v1(1075,805)
  Signal Layer 1 w40: v1(840,1235) 840,1155.04 885.04,1110 955,1110 1075,990 v1(1075,805)
  Bottom Layer w10: Q8.4@689.41,572.4 689.88,572.87 v2(689.88,620) ; Q8.1@740.59,497.6 897.6,497.6 1015,615 1015,790 1030,805 v1(1075,805)
  Bottom Layer w25: v1(840,1235) C2.1@840,1292.44
PR36: C3.1 D2.2 D6.1 Q9.1 Q9.4 T1.21 U1.15 U1.16 | length 2120.4
  Top Layer w25: v1@690,1225 v1@690.04,1224.96 ; v1(690,1235) T1.21@690.04,1118.63
  Top Layer w38: U1.15@837.48,680.94 U1.16@930,680.94 1042.76,680.94 1075,648.7 v1(1075,615)
  Signal Layer 1 w10: v2(690,820) 690,760 740,710 v2(740,660) 980,660 1025,615 v1(1075,615)
  Signal Layer 1 w40: v1(690,1235) 755,1300 875,1300 1150,1025 1150,690 v1(1075,615)
  Bottom Layer w10: Q9.1@689.41,777.4 690,777.99 v2(690,820) ; v2(740,660) 740.59,660.59 Q9.4@740.59,702.6
  Bottom Layer w25: v1(690,1235) C3.1@690,1292.44
PR45: C4.1 D3.2 D7.1 Q10.1 Q10.4 T1.18 U2.13 U2.14 | length 3461.5
  Top Layer w25: v1@540,1225 v1@540.04,1224.96 ; v1(540,1235) T1.18@540.04,1118.63
  Top Layer w38: U2.14@837.48,360 U2.13@930,360 1049.54,360 1075,385.46 v1(1075,425)
  Signal Layer 1 w10: v2(690,240) 655,240 635,260 635,480 655,500 930,500 1005,425 v1(1075,425)
  Signal Layer 1 w40: v1(540,1235) 680,1375 925,1375 1225,1075 1225,575 v1(1075,425)
  Bottom Layer w10: Q10.4@689.41,197.4 690,197.99 v2(690,240) ; Q10.1@740.59,122.6 992.6,122.6 1015,145 1015,410.46 1029.54,425 v1(1075,425)
  Bottom Layer w25: v1(540,1235) C4.1@540,1292.44
PR78: C5.1 D4.2 D8.1 Q11.1 Q11.4 T1.15 U2.15 U2.16 | length 3218.9
  Top Layer w25: v1(390,1235) T1.15@390.04,1118.63
  Top Layer w38: U2.15@837.48,300.94 U2.16@930,300.94 1052.11,300.94 1075,278.06 v1(1075,235)
  Signal Layer 1 w10: v2(675,440) 740,375 v2(740,280) 955,280 1000,235 v1(1075,235)
  Signal Layer 1 w40: v1(390,1235) 605,1450 975,1450 1300,1125 1300,460 v1(1075,235)
  Bottom Layer w10: v2(675,440) 689.41,425.59 Q11.1@689.41,397.4 ; v2(740,280) 740.59,280.59 Q11.4@740.59,322.6
  Bottom Layer w25: v1(390,1235) 390,1277.44 C5.1@405,1292.44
